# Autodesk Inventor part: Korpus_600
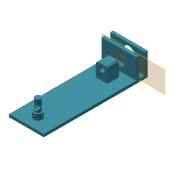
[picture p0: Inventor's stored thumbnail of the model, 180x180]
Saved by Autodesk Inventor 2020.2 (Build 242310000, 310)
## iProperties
Created: 2014-12
Part Number: Korpus_600
Material: Ogólny
Document SubType Name: Modeling
Designer: F.Stasiak
Density: 1 g/cm^3
Appearance: Niebieska z odcieniem szarości
Catalog Web Link: www.expertbooks.pl
Manager: www.cadconsulting.pl
Company: Fabian Stasiak CAD Consulting
Author: F.Stasiak
Subject: Zbiór ćwiczeń. Autodesk Inventor 2020. Kurs Professional
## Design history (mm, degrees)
sketch "Szkic1"
  geometry: L1 (-30, 90)-(30, 90); L2 (30, 90)-(30, -90); L3 (30, -90)-(-30, -90); L4 (-30, -90)-(-30, 90); L5 (-30, 90)-(30, -90); L6 (30, 90)-(-30, -90); 1 further point
  constraints: 12 end point, 2 midpoint, 2 parallel, 1 horizontal, 1 perpendicular
  dimensions: "d0" = 60 distance of L2.end L3.end; "d1" = 180 distance of L1.end L2.end
extrude "Wyciągnięcie proste1" new body sketch "Szkic1" distance "d2" = 5; taper "d3" = 0 deg
sketch "Szkic6"
  geometry: L1 (-30, -90)-(30, -90) reference; L2 (-30, -90)-(-30, 90) reference; C1 r 7.5 at (0, -70); 1 further point
  constraints: 1 centre point, 1 vertical alignment
  dimensions: "d29" = 15 diameter of C1; "d30" = 20 distance from line of L1 C1.centre
extrude "Wyciągnięcie proste6" join sketch "Szkic6" distance "d32" = 10; taper "d33" = 0 deg
sketch "Szkic7"
  geometry: C1 r 7.5 at (0, 0) reference; C2 r 5 at (0, 0); 1 further point
  constraints: 1 centre point, 1 coincident
  dimensions: "d34" = 10 diameter of C2
extrude "Wyciągnięcie proste7" join sketch "Szkic7" distance "d35" = 20; taper "d36" = 0 deg
sketch "Szkic8"
  geometry: L1 (-10, 60)-(10, 60); L2 (10, 60)-(10, 40); L3 (10, 40)-(-10, 40); L4 (-10, 40)-(-10, 60); L5 (0, 40)-(0, 60); L6 (30, -90)-(-30, -90) reference; C1 r 7.5 at (0, -70) reference; 1 further point
  constraints: 10 end point, 2 midpoint, 2 parallel, 1 horizontal, 1 perpendicular, 1 point on line
  dimensions: "d37" = 20 distance of L2.end L3.end; "d38" = 20 distance of L1.end L2.end; "d39" = 150 distance between parallel lines of L1 L6
extrude "Wyciągnięcie proste8" join sketch "Szkic8" distance "d40" = 25; taper "d41" = 0 deg
hole "Otwór2" diameter "d44" = 10; stored, may be unused: countersink angle "d48" = 90 deg, drill point angle "d50" = 118 deg; dims "d42" = 7.5, "d43" = 10 (= 0.5 x d37), "d45" = 6, "d46" = 4, "d47" = 2, "d49" = 8
fillet "Zaokrąglenie2" dims "d51" = 5
sketch "Szkic11"
  geometry: L1 (30, 90)-(-30, 90) reference; L2 (-30, 90)-(30, 90); L3 (30, 90)-(30, 85); L4 (30, 85)-(-30, 85); L5 (-30, 85)-(-30, 90); L6 (30, -90)-(30, 90) reference; 1 further point
  constraints: 8 end point, 2 parallel, 1 collinear, 1 horizontal, 1 perpendicular
  dimensions: "d60" = 5 distance of L2.end L3.end
extrude "Wyciągnięcie proste11" join sketch "Szkic11" distance "d61" = 35; taper "d62" = 0 deg
sketch "Szkic12"
  geometry: C1 r 10.5 at (30, 17.5) reference; 1 further point
extrude "Wyciągnięcie proste12" cut sketch "Szkic12" extent not by distance; stored distance "d63" = 35; taper "d64" = 0 deg
chamfer "Faza1" distance "d65" = 3; stored, may be unused: second distance "d66" = 2, angle "d67" = 45 deg
node "Płaszczyzna konstrukcyjna1"
sketch "Szkic13"
  geometry: L1 (60, 0)-(0, 0) reference; L2 (60, 0)-(60, 35) reference; L3 (0, 35)-(60, 35) reference; L4 (0, 0)-(0, 35) reference; C1 r 10.5 at (30, 17.5) reference; C2 r 13.5 at (30, 17.5) reference; 1 further point
extrude "Wyciągnięcie proste13" join sketch "Szkic13" distance "d69" = 5; taper "d70" = 0 deg
chamfer "Faza2" distance "d71" = 3; stored, may be unused: second distance "d72" = 2, angle "d73" = 45 deg
node "Bryła1"
node "Pętla rzutowana2"
node "Odniesienie2"
node "Odniesienie3"
